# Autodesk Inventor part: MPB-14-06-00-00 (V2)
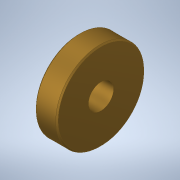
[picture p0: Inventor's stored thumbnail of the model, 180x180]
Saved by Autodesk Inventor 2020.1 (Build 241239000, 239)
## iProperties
Created: 2020-04
Part Number: MPB-14-06-00-00 (V2)
Material: Brass
Document SubType Name: Modeling
Designer: Safarabadi
Density: 8.47 g/cm^3
Appearance: Brass - Satin
Author: Safarabadi
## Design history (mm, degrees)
derived "MPB-14-06-00-00.ipt"
feature "Solid1::MPB-14-06-00-00.ipt" dims "d0" = 10
tag "TaggingFeature1"
body "Solid1"
